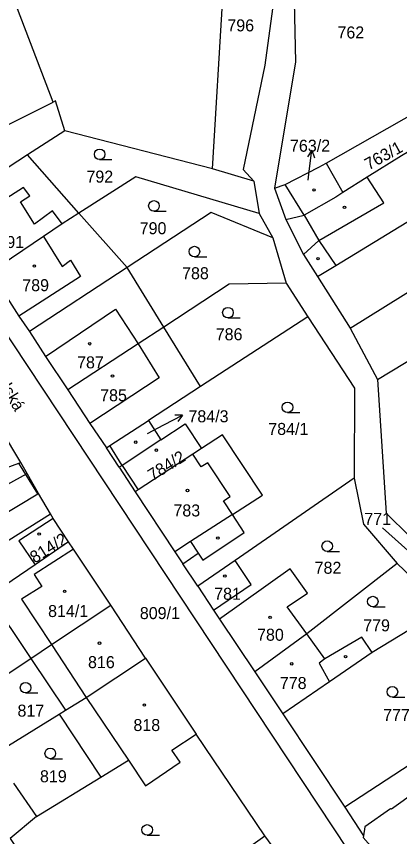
# Model space of a CAD drawing. Extents: x -776701 to -776081, y -974398 to -973771.
# Drawn here: x -776283.7 to -776229.3, y -973949 to -973832.8 of the extents above; entities that cross this region are included whole.
import ezdxf

# ---------------------------------------------------------------- set-up
doc = ezdxf.new("R2010")
doc.units = 0
for name, color, linetype in [('Hranice parcel', 7, 'Continuous'), ('Parcelní čísla', 7, 'Continuous'), ('Pop  PČ popisy', 7, 'Continuous'), ('Vnitřní kresba', 7, 'Continuous'), ('Značky budov', 7, 'Continuous'), ('Značky kultur', 7, 'Continuous')]:
    doc.layers.add(name, color=color, linetype=linetype)

msp = doc.modelspace()

# ---------------------------------------------------------------- linework, layer by layer
at = {"layer": 'Hranice parcel'}
for p, q in [((-776255.89, -973854.42), (-776253.42, -973814.06)), ((-776278.45, -973844.96), (-776285.43, -973826.82)), ((-776239.75, -973853.59), (-776220.95, -973842.92)), ((-776276.81, -973849.02), (-776282.1, -973852.45)), ((-776255.89, -973854.42), (-776276.81, -973849.02)), ((-776282.1, -973852.45), (-776293.48, -973859.83)), ((-776274.82, -973860.69), (-776282.1, -973852.45)), ((-776250.03, -973856.15), (-776255.89, -973854.42)), ((-776239.75, -973853.59), (-776237.38, -973857.77)), ((-776250.03, -973856.15), (-776249.26, -973860.74)), ((-776268, -973868.41), (-776274.82, -973860.69)), ((-776249.26, -973860.74), (-776247.3, -973864.21)), ((-776245.46, -973861.6), (-776242.9, -973861)), ((-776247.3, -973864.21), (-776245.45, -973870.6)), ((-776268, -973868.41), (-776281.82, -973877.48)), ((-776262.79, -973876.85), (-776268, -973868.41)), ((-776232.47, -973884.28), (-776205.52, -973867.88)), ((-776240.99, -973869.69), (-776236.37, -973876.99)), ((-776245.45, -973870.6), (-776242.38, -973875.37)), ((-776242.38, -973875.37), (-776257.6, -973885.27)), ((-776257.6, -973885.27), (-776262.79, -973876.85)), ((-776236.37, -973876.99), (-776232.47, -973884.28)), ((-776257.6, -973885.27), (-776264.93, -973890.05)), ((-776264.93, -973890.05), (-776263.18, -973892.81)), ((-776283.07, -973896.02), (-776285.78, -973891.43)), ((-776269.1, -973896.7), (-776270.91, -973893.94)), ((-776283.35, -973896.13), (-776283.07, -973896.02)), ((-776280.64, -973900.45), (-776283.35, -973896.13)), ((-776280.55, -973900.39), (-776283.07, -973896.02)), ((-776269.1, -973896.7), (-776266.82, -973900.17)), ((-776235.77, -973898.22), (-776252.65, -973909.91)), ((-776296.67, -973910.04), (-776280.64, -973900.45)), ((-776280.55, -973900.39), (-776280.64, -973900.45)), ((-776278.87, -973903.3), (-776280.55, -973900.39)), ((-776294.6, -973913.15), (-776278.87, -973903.3)), ((-776278.46, -973903.93), (-776278.87, -973903.3)), ((-776276.31, -973907.24), (-776278.46, -973903.93)), ((-776276.31, -973907.24), (-776281, -973910.5)), ((-776257.98, -973913.55), (-776260.09, -973910.39)), ((-776252.65, -973909.91), (-776257.98, -973913.55)), ((-776229.69, -973910.31), (-776242.52, -973920.28)), ((-776229.69, -973910.31), (-776223.06, -973916.72)), ((-776257.98, -973913.55), (-776255.73, -973916.95)), ((-776265.39, -973923.75), (-776270.29, -973916.24)), ((-776255.73, -973916.95), (-776254.89, -973918.2)), ((-776223.06, -973916.72), (-776233.23, -973922.95)), ((-776254.89, -973918.2), (-776249.88, -973925.66)), ((-776242.52, -973920.28), (-776249.88, -973925.66)), ((-776233.23, -973922.95), (-776234.71, -973920.78)), ((-776233.23, -973922.95), (-776239.28, -973927.09)), ((-776285.7, -973926.49), (-776281.65, -973923.77)), ((-776281.65, -973923.77), (-776276.73, -973931.11)), ((-776265.39, -973923.75), (-776258.19, -973934.5)), ((-776249.88, -973925.66), (-776245.91, -973931.61)), ((-776239.28, -973927.09), (-776245.91, -973931.61)), ((-776277.63, -973931.67), (-776276.73, -973931.11)), ((-776284.82, -973936.13), (-776277.63, -973931.67)), ((-776277.63, -973931.67), (-776271.71, -973940.6)), ((-776245.91, -973931.61), (-776237.1, -973944.84)), ((-776217.53, -973932.01), (-776237.1, -973944.84)), ((-776248.44, -973948.9), (-776258.19, -973934.5)), ((-776280.81, -973946.19), (-776271.71, -973940.6)), ((-776284.08, -973941.43), (-776280.81, -973946.19)), ((-776237.1, -973944.84), (-776234.47, -973948.93)), ((-776273.08, -973966.36), (-776248.44, -973948.9)), ((-776241.31, -973958.73), (-776248.44, -973948.9))]:
    msp.add_line(p, q, dxfattribs=at)
for points in [[(-776242.84, -973810.95), (-776244.28, -973830.76), (-776244.11, -973839.24), (-776247.09, -973857.16), (-776245.46, -973861.6)], [(-776245.02, -973814.37), (-776248.48, -973839.74), (-776251.52, -973854.49), (-776250.03, -973856.15)], [(-776300.69, -973843.77), (-776294.45, -973841.67), (-776290.81, -973840.44), (-776286.94, -973849.17), (-776278.45, -973844.96)], [(-776276.81, -973849.02), (-776278.12, -973844.8), (-776278.45, -973844.96)], [(-776218.81, -973846.53), (-776229.07, -973852.55), (-776233.95, -973855.6), (-776237.38, -973857.77)], [(-776240.99, -973869.69), (-776238.41, -973868.12), (-776223.83, -973859.23), (-776214.18, -973853.35)], [(-776242.9, -973861), (-776245.58, -973856.64), (-776240.79, -973854.18), (-776239.75, -973853.59)], [(-776249.26, -973860.74), (-776266.75, -973855.57), (-776274.82, -973860.69)], [(-776237.38, -973857.77), (-776238.39, -973858.41), (-776242.9, -973861)], [(-776236.37, -973876.99), (-776219.2, -973866.3), (-776209.82, -973860.47)], [(-776274.82, -973860.69), (-776277.19, -973862.19), (-776279.86, -973863.99), (-776287.36, -973869.07)], [(-776247.3, -973864.21), (-776256.08, -973860.59), (-776268, -973868.41)], [(-776245.46, -973861.6), (-776242.98, -973866.53), (-776240.99, -973869.69)], [(-776287.36, -973869.07), (-776283.32, -973875.27), (-776281.82, -973877.48)], [(-776245.45, -973870.6), (-776253.52, -973870.77), (-776262.79, -973876.85)], [(-776242.38, -973875.37), (-776235.75, -973885.47), (-776235.77, -973898.22)], [(-776281.82, -973877.48), (-776279.55, -973880.99), (-776276.39, -973885.7)], [(-776262.79, -973876.85), (-776266.42, -973879.21), (-776276.39, -973885.7)], [(-776232.47, -973884.28), (-776231.24, -973903.2), (-776227.9, -973906.51)], [(-776276.39, -973885.7), (-776273.25, -973890.47), (-776270.91, -973893.94)], [(-776270.91, -973893.94), (-776270.43, -973893.62), (-776264.93, -973890.05)], [(-776263.18, -973892.81), (-776259.73, -973890.53), (-776257.44, -973894.05)], [(-776263.18, -973892.81), (-776268.67, -973896.42), (-776269.1, -973896.7)], [(-776251.41, -973905.92), (-776253.03, -973903.37), (-776248.81, -973900.64), (-776254.47, -973892.12), (-776257.44, -973894.05)], [(-776257.44, -973894.05), (-776258.67, -973894.86), (-776266.4, -973899.9), (-776266.82, -973900.17)], [(-776306.21, -973896.53), (-776304.69, -973901.67), (-776303.49, -973901.31), (-776303.42, -973901.55), (-776289.15, -973897.92), (-776289.19, -973897.77), (-776285.12, -973896.75), (-776283.35, -973896.13)], [(-776235.77, -973898.22), (-776234.49, -973904.75), (-776229.69, -973910.31)], [(-776266.82, -973900.17), (-776261.23, -973908.67), (-776260.09, -973910.39)], [(-776278.46, -973903.93), (-776283.35, -973907.1), (-776281, -973910.5)], [(-776260.09, -973910.39), (-776257.91, -973908.86), (-776257.23, -973909.86), (-776251.41, -973905.92)], [(-776270.29, -973916.24), (-776275.61, -973908.29), (-776276.31, -973907.24)], [(-776255.73, -973916.95), (-776250.38, -973913.32), (-776252.65, -973909.91)], [(-776281, -973910.5), (-776287.6, -973914.95), (-776281.65, -973923.77)], [(-776242.52, -973920.28), (-776245.28, -973916.46), (-776242.4, -973914.54), (-776244.86, -973911.08), (-776254.89, -973918.2)], [(-776281.65, -973923.77), (-776278.7, -973921.8), (-776270.29, -973916.24)], [(-776234.71, -973920.78), (-776239.94, -973923.85), (-776242.52, -973920.28)], [(-776276.73, -973931.11), (-776273.8, -973929.3), (-776265.39, -973923.75)], [(-776271.71, -973940.6), (-776267.81, -973938.2), (-776265.38, -973941.82), (-776260.46, -973938.49), (-776261.64, -973936.79), (-776258.19, -973934.5)], [(-776221.22, -973938.85), (-776226.99, -973942.64), (-776230.52, -973945.14)], [(-776230.52, -973945.14), (-776230.63, -973945.06), (-776234.28, -973947.62), (-776234.47, -973948.93)], [(-776280.81, -973946.19), (-776284.56, -973949.27), (-776282.89, -973951.76)], [(-776234.47, -973948.93), (-776234.5, -973949.16), (-776231.62, -973952.39), (-776231.48, -973952.27)]]:
    msp.add_lwpolyline(points, dxfattribs=at)
at = {"layer": 'Pop  PČ popisy'}
for p, q in [((-776241.78, -973851.78), (-776242.4, -973852.71)), ((-776242.15, -973854.76), (-776241.78, -973851.78)), ((-776241.78, -973851.78), (-776241.41, -973852.84)), ((-776242.3, -973856), (-776242.15, -973854.76)), ((-776262.77, -973890.7), (-776260.12, -973889.29)), ((-776260.12, -973889.29), (-776261.24, -973889.32)), ((-776260.12, -973889.29), (-776260.77, -973890.2)), ((-776265.11, -973891.92), (-776262.77, -973890.7)), ((-776282.28, -973897.67), (-776282.31, -973897.69)), ((-776282.31, -973897.69), (-776284.94, -973899.15))]:
    msp.add_line(p, q, dxfattribs=at)
at = {"layer": 'Vnitřní kresba'}
for p, q in [((-776231.6, -973859.25), (-776233.95, -973855.6)), ((-776247.09, -973857.16), (-776245.58, -973856.64)), ((-776282.69, -973857.05), (-776291.54, -973862.76)), ((-776281.78, -973858.24), (-776282.69, -973857.05)), ((-776283.1, -973859.1), (-776281.78, -973858.24)), ((-776281.1, -973862.25), (-776283.1, -973859.1)), ((-776240.8, -973864.55), (-776231.6, -973859.25)), ((-776278.57, -973860.37), (-776281.1, -973862.25)), ((-776277.19, -973862.19), (-776278.57, -973860.37)), ((-776236.59, -973950.99), (-776296.16, -973861.12)), ((-776242.9, -973861), (-776240.8, -973864.55)), ((-776279.86, -973863.99), (-776277.2, -973868.25)), ((-776242.98, -973866.53), (-776240.8, -973864.55)), ((-776240.8, -973864.55), (-776238.41, -973868.12)), ((-776277.2, -973868.25), (-776275.99, -973867.34)), ((-776275.99, -973867.34), (-776274.6, -973869.68)), ((-776274.6, -973869.68), (-776283.32, -973875.27)), ((-776279.55, -973880.99), (-776269.65, -973874.3)), ((-776269.65, -973874.3), (-776266.42, -973879.21)), ((-776266.42, -973879.21), (-776263.44, -973884)), ((-776263.44, -973884), (-776273.25, -973890.47)), ((-776268.67, -973896.42), (-776270.43, -973893.62)), ((-776257.48, -973896.64), (-776258.67, -973894.86)), ((-776268.67, -973896.42), (-776266.4, -973899.9)), ((-776256.54, -973896.05), (-776257.48, -973896.64)), ((-776253.35, -973900.84), (-776256.54, -973896.05)), ((-776254.3, -973901.46), (-776253.35, -973900.84)), ((-776253.03, -973903.37), (-776254.3, -973901.46)), ((-776253.03, -973903.37), (-776258.99, -973907.22)), ((-776258.99, -973907.22), (-776261.23, -973908.67)), ((-776258.99, -973907.22), (-776257.91, -973908.86)), ((-776275.61, -973908.29), (-776281.18, -973911.9)), ((-776281.18, -973911.9), (-776280.1, -973913.58)), ((-776280.1, -973913.58), (-776282.95, -973915.38)), ((-776282.95, -973915.38), (-776278.7, -973921.8)), ((-776278.7, -973921.8), (-776273.8, -973929.3)), ((-776239.94, -973923.85), (-776240.75, -973924.45)), ((-776240.75, -973924.45), (-776239.28, -973927.09)), ((-776273.8, -973929.3), (-776267.81, -973938.2))]:
    msp.add_line(p, q, dxfattribs=at)
at = {"layer": 'Značky budov'}
for centre in [(-776241.48, -973857.4), (-776237.16, -973859.86), (-776240.91, -973867.14), (-776281.14, -973868.18), (-776273.29, -973879.2), (-776270.06, -973883.77), (-776266.76, -973893.14), (-776263.84, -973894.27), (-776259.42, -973899.98), (-776280.46, -973906.16), (-776255.12, -973906.72), (-776254.13, -973912.1), (-776276.85, -973914.28), (-776247.71, -973917.95), (-776271.9, -973921.61), (-776244.65, -973924.54), (-776237.01, -973923.53), (-776265.53, -973930.38)]:
    msp.add_circle(centre, 0.175, dxfattribs=at)
at = {"layer": 'Značky kultur'}
for p, q in [((-776271.88, -973853.11), (-776270.13, -973853.11)), ((-776264.18, -973860.42), (-776262.43, -973860.42)), ((-776258.44, -973866.89), (-776256.69, -973866.89)), ((-776253.69, -973875.54), (-776251.94, -973875.54)), ((-776245.24, -973888.95), (-776243.49, -973888.95)), ((-776231.75, -973905.28), (-776227.29, -973909.3)), ((-776239.61, -973908.62), (-776237.86, -973908.62)), ((-776233.15, -973916.47), (-776231.4, -973916.47)), ((-776282.38, -973928.67), (-776280.63, -973928.67)), ((-776230.37, -973929.26), (-776228.62, -973929.26)), ((-776278.88, -973937.98), (-776277.13, -973937.98)), ((-776265.14, -973948.82), (-776263.39, -973948.82))]:
    msp.add_line(p, q, dxfattribs=at)
for centre in [(-776271.88, -973852.36), (-776264.18, -973859.67), (-776258.44, -973866.14), (-776253.69, -973874.79), (-776245.24, -973888.2), (-776239.61, -973907.87), (-776233.15, -973915.72), (-776282.38, -973927.92), (-776230.37, -973928.51), (-776278.88, -973937.23), (-776265.14, -973948.07)]:
    msp.add_circle(centre, 0.75, dxfattribs=at)

# ---------------------------------------------------------------- texts
at = {"layer": 'Parcelní čísla'}
for s, p in [('796', (-776253.77, -973834.94)), ('762', (-776238.16, -973835.94)), ('763/2', (-776244.89, -973851.99)), ('792', (-776273.75, -973856.37)), ('790', (-776266.2, -973863.68)), ('791', (-776286.38, -973865.63)), ('788', (-776260.19, -973870.05)), ('789', (-776282.85, -973871.75)), ('786', (-776255.42, -973878.7)), ('787', (-776275.08, -973882.68)), ('785', (-776271.81, -973887.34)), ('784/3', (-776259.29, -973890.32)), ('784/1', (-776247.97, -973892.11)), ('783', (-776261.42, -973903.66)), ('771', (-776234.35, -973904.85)), ('782', (-776241.4, -973911.78)), ('781', (-776255.64, -973915.47)), ('814/1', (-776279.19, -973917.91)), ('809/1', (-776266.18, -973918.2)), ('779', (-776234.51, -973919.94)), ('780', (-776249.56, -973921.27)), ('816', (-776273.53, -973925.15)), ('778', (-776246.33, -973928.11)), ('817', (-776283.53, -973932.02)), ('777', (-776231.68, -973932.62)), ('818', (-776267.09, -973934.06)), ('819', (-776280.34, -973941.32))]:
    msp.add_text(s, height=1.7, dxfattribs=at).set_placement(p)
for s, rotation, p in [('763/1', 29, (-776233.72, -973854.65)), ('784/2', 32, (-776264.37, -973898.68)), ('814/2', 32, (-776281.09, -973910.35))]:
    msp.add_text(s, height=1.7, rotation=rotation, dxfattribs=at).set_placement(p)
at = {"layer": 'Pop  PČ popisy'}
msp.add_text('Sokolská', height=1.7, rotation=301, dxfattribs=at).set_placement((-776288.61, -973880.99))

doc.saveas('drawing.dxf')
